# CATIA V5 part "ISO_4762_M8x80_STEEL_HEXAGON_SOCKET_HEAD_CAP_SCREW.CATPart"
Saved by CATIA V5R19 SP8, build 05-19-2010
Part number: ISO 4762 SCREW M8x80 STEEL HEXAGON SOCKET HEAD CAP
Nomenclature: 26
Publications: "Mating Face", "Axis"
Bounding box of the stored display mesh (mm): x -80 to 8, y -6.5 to 6.5, z -6.49 to 6.49
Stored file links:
  C:\Users\rphgr\Desktop\0_Tapis_TC520B_vitesse\ISO_4762_M8x80_STEEL_HEXAGON_SOCKET_HEAD_CAP_SCREW.CATPart
  D:\Programmes\DassaultSysteme\win_b64\startup\components\MechanicalStandardParts\EN_Standards\Design_Tables\EN_ISO_4762_HEXAGON_SOCKET_HEAD_CAP_SCREW.txt
  C:\Program Files\Dassault Systemes\B19\win_b64\startup\components\MechanicalStandardParts\ISO_Standards\Design_Tables\ISO_4762_HEXAGON_SOCKET_HEAD_CAP_SCREW.txt
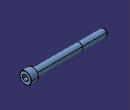
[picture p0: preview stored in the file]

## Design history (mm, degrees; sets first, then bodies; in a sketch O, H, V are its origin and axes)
Parameters
  d_dia = 8 mm
  l_nom = 80 mm
  k_head_depth_max = 8 mm
  s_nom = 6 mm
  r_min = 0.4 mm
  ds_max = 8 mm
  e = 6.863 mm
  t_min = 4 mm
  p_pitch = 1.25 mm
  Threading = 28 mm
  dk_max = 13 mm
Body1 "PartBody" (main body)
  Sketch1 on yz-plane, origin (0, 0, 0), H (0, 1, 0), V (0, 0, 1)
    circle A1 centre (0, 0) radius 6.5
    radius A1 = 6.5 {= dk_max /2}
  Pad1: profile Sketch1, direction (1, 0, 0), length 8 {= k_head_depth_max}
  Fillet1: radius 0.4 {= r_min}, on edge [face of Pad1 | face of Pad1]
  Body2
    Sketch2 on face of Pad1, origin (8, 0, 0), H (0, 1, 0), V (0, 0, 1)
      point P1 (3, -1.7321)
      point P2 (3, 1.7321)
      point P3 (0, 3.4641)
      point P4 (-3, 1.7321)
      point P5 (-3, -1.7321)
      point P6 (0, -3.4641)
      point P7 (3, 0)
      line L1 (3, -1.7321) -> (3, 1.7321)
      line L2 (3, 1.7321) -> (0, 3.4641)
      line L3 (0, 3.4641) -> (-3, 1.7321)
      line L4 (-3, 1.7321) -> (-3, -1.7321)
      line L5 (-3, -1.7321) -> (0, -3.4641)
      line L6 (0, -3.4641) -> (3, -1.7321)
      construction line L7 (0, 0) -> (3, 0)
      construction circle A1 centre (0, 0) radius 3.4641
      construction arc A2 centre (-3, -1.7321) radius 3.4641 from (-3, 1.7321) to (0, -3.4641) cw
      construction arc A3 centre (3, 1.7321) radius 3.4641 from (0, 3.4641) to (3, -1.7321) ccw
      point P8 (-3, -1.7321)
      point P9 (3, 1.7321)
      distance L1 L4 = 6 {= s_nom}
      horizontal: L7 H
      coincidence: A1 P1, A1 P2, A1 P3, A1 P4, A1 P5, A1 P6, A2 P4, A2 P6, A2 O, P8 P5, A3 P3, A3 P1, A3 O, P9 P2
      midpoint: P7 L1
    Pad2: profile Sketch2, direction (-1, 0, 0), length 5.9778 {= t_min +(e /3.47)}
    Body3
      Sketch3 on zx-plane, origin (0, 0, 0), H (-1, 0, 0), V (0, 0, 1)
        point P1 (-2.0188, 0)
        line L1 (-2.0188, 0) -> (-4, 3.4315)
        line L2 (-4, 3.4315) -> (-8, 3.4315)
        line L3 (-8, 3.4315) -> (-8, 0)
        axis line L4 (-46.2384, 0) -> (26.3409, 0)
        reference projected line E1 (-8, -6.9227) -> (-8, 6.9227) from edge [face of Pad2 | face of Pad2]
        length L2 = 4 {= t_min}
        angle L1 L4 = 60
        distance L2 L4 = 3.4315 {= e /2}
        horizontal: L2 H, L4 H
        perpendicularity: L3 L2
        fix: L4
        coincidence: L3 E1, P1 L4
      Shaft1: profile Sketch3, axis Sketch3.L4, angle 360
    Intersect1: tool Body3
  Remove1: tool Body2
  Sketch4 on xy-plane, origin (0, 0, 0), H (1, 0, 0), V (0, 1, 0)
    line L1 (0, 0) -> (0, 4)
    line L2 (0, 4) -> (-52, 4)
    line L3 (-52, 4) -> (-52, 3.9024)
    line L4 (-52, 3.9024) -> (-80, 3.9024)
    line L5 (-80, 3.9024) -> (-80, 0)
    axis line L6 (-192.3446, 0) -> (99.1594, 0)
    distance L5 L1 = 80 {= l_nom}
    distance L3 L5 = 28 {= Threading}
    distance L2 L6 = 4 {= ds_max /2}
    distance L4 L6 = 3.9024 {= d_dia /2.05}
    vertical: L1 V, L3 V, L5 V
    horizontal: L2 H, L4 H, L6 H
    fix: L6
  Shaft2: profile Sketch4, axis Sketch4.L6, angle 360
  Fillet2: radius 0.4 {= r_min}, on edge [face of Shaft2 | face of Pad1]
  Chamfer1: length 1.25 {= p_pitch}, angle 45, on edge [face of Shaft2 | face of Shaft2]
  Thread1: diameter 7.8049 {= d_dia /1.025}, depth 28 {= Threading}, pitch 1, on face of Shaft2, from face of Shaft2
